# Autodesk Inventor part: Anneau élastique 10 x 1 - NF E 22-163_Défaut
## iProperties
Shininess: 64.0
Length Units: 11269
Angle Units: 11279
Time Units: 11290
Mass Units: 11283
Length Display Precision: 3
Angle Display Precision: 2
Compacted: True
Part Number: Anneau élastique 10 x 1 - NF E 22-163_Défaut
Document SubType Name: Modeling
Created: 2006-01
Material: Par défaut
Designer: riri
Density: 0.0
Volumn: 0.0
Area: 0.0
PropertySet Name: Model Information
Control State: 0
Master: False
Checked Out: False
Author: riri
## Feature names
1. Base1
